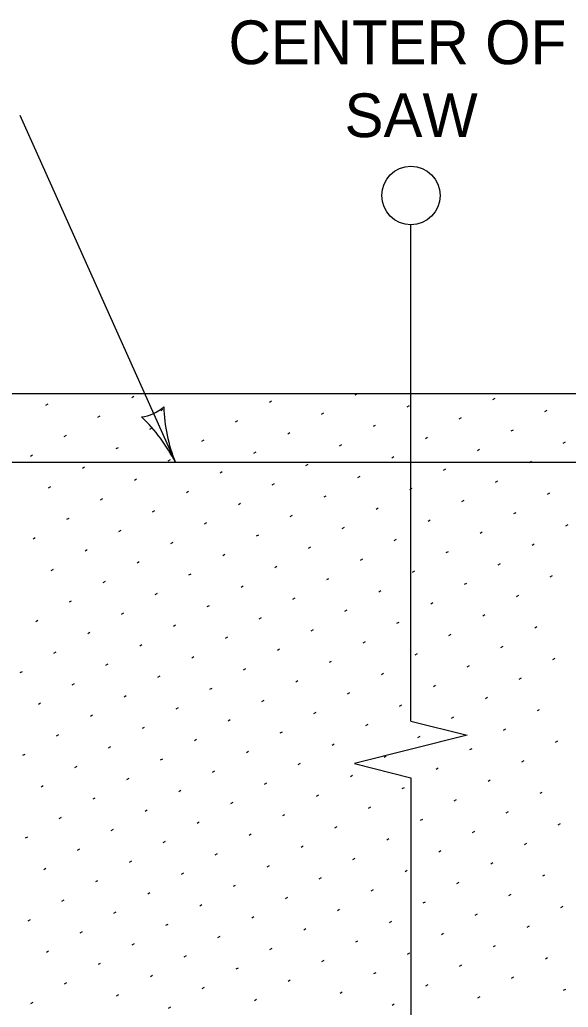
# Model space of a CAD drawing. Extents: x 49991.4 to 50021, y 49987.6 to 50011.4.
# Drawn here: x 50004.089 to 50004.842, y 49994.036 to 49995.39 of the extents above; entities that cross this region are included whole.
import ezdxf

# ---------------------------------------------------------------- set-up
doc = ezdxf.new("R2010")
doc.units = 0
for name, color, linetype in [('Level 1', 7, 'Continuous'), ('Level 15', 7, 'Continuous'), ('Level 3', 7, 'Continuous')]:
    doc.layers.add(name, color=color, linetype=linetype)

msp = doc.modelspace()

# ---------------------------------------------------------------- linework, layer by layer
at = {"layer": 'Level 1'}
for p, q in [((50002.5376, 49994.8772), (50004.5362, 49994.8772)), ((50004.5362, 49994.8772), (50008.0315, 49994.8772)), ((50008.0315, 49994.7828), (50001.9803, 49994.7828))]:
    msp.add_line(p, q, dxfattribs=at)
msp.add_ellipse((50004.6259, 49996.2377), major_axis=(0, -2.952), ratio=0.83118, start_param=5.208402, end_param=6.283185, dxfattribs=at)
at = {"layer": 'Level 15'}
msp.add_line((50004.6259, 49994.3507), (50004.6259, 49994.0829), dxfattribs=at)
at = {"layer": 'Level 3'}
for p, q in [((50004.0891, 49995.2588), (50004.3027, 49994.7828)), ((50004.6259, 49994.4281), (50004.6259, 49995.1088)), ((50004.5495, 49994.8757), (50004.5521, 49994.8772)), ((50004.1251, 49994.8616), (50004.1281, 49994.8634)), ((50004.2428, 49994.8718), (50004.2458, 49994.8736)), ((50004.4318, 49994.8655), (50004.4348, 49994.8672)), ((50004.7385, 49994.8693), (50004.7415, 49994.8711)), ((50004.2834, 49994.8536), (50004.2855, 49994.8564)), ((50004.5031, 49994.8489), (50004.5062, 49994.8507)), ((50004.6208, 49994.8591), (50004.6238, 49994.8609)), ((50004.8098, 49994.8528), (50004.8128, 49994.8545)), ((50004.1964, 49994.8451), (50004.1995, 49994.8468)), ((50004.3854, 49994.8387), (50004.3885, 49994.8405)), ((50004.6921, 49994.8426), (50004.6952, 49994.8443)), ((50004.2678, 49994.8285), (50004.2708, 49994.8303)), ((50004.4568, 49994.8222), (50004.4598, 49994.8239)), ((50004.5745, 49994.8324), (50004.5775, 49994.8341)), ((50004.7635, 49994.826), (50004.7665, 49994.8278)), ((50004.1501, 49994.8183), (50004.1531, 49994.8201)), ((50004.3391, 49994.812), (50004.3421, 49994.8137)), ((50004.6458, 49994.8158), (50004.6488, 49994.8176)), ((50004.8348, 49994.8095), (50004.8378, 49994.8112)), ((50004.2214, 49994.8018), (50004.2245, 49994.8035)), ((50004.4104, 49994.7954), (50004.4135, 49994.7972)), ((50004.5281, 49994.8056), (50004.5312, 49994.8074)), ((50004.7171, 49994.7993), (50004.7202, 49994.801)), ((50004.1038, 49994.7916), (50004.1068, 49994.7933)), ((50004.2928, 49994.7852), (50004.2958, 49994.787)), ((50004.5995, 49994.7891), (50004.6025, 49994.7908)), ((50004.7885, 49994.7827), (50004.7915, 49994.7845)), ((50004.1751, 49994.775), (50004.1781, 49994.7768)), ((50004.3641, 49994.7687), (50004.3671, 49994.7704)), ((50004.4818, 49994.7789), (50004.4848, 49994.7806)), ((50004.6708, 49994.7725), (50004.6738, 49994.7743)), ((50004.2464, 49994.7585), (50004.2495, 49994.7602)), ((50004.5531, 49994.7623), (50004.5562, 49994.7641)), ((50004.7421, 49994.756), (50004.7452, 49994.7577)), ((50004.1288, 49994.7483), (50004.1318, 49994.75)), ((50004.3178, 49994.7419), (50004.3208, 49994.7437)), ((50004.4354, 49994.7521), (50004.4385, 49994.7539)), ((50004.6245, 49994.7458), (50004.6275, 49994.7475)), ((50004.2001, 49994.7317), (50004.2031, 49994.7335)), ((50004.5068, 49994.7356), (50004.5098, 49994.7373)), ((50004.6958, 49994.7292), (50004.6988, 49994.731)), ((50004.8135, 49994.7394), (50004.8165, 49994.7412)), ((50004.2714, 49994.7152), (50004.2745, 49994.7169)), ((50004.3891, 49994.7254), (50004.3921, 49994.7271)), ((50004.5781, 49994.719), (50004.5812, 49994.7208)), ((50004.7671, 49994.7127), (50004.7702, 49994.7144)), ((50004.1538, 49994.705), (50004.1568, 49994.7067)), ((50004.4604, 49994.7088), (50004.4635, 49994.7106)), ((50004.6495, 49994.7025), (50004.6525, 49994.7042)), ((50004.2251, 49994.6884), (50004.2281, 49994.6902)), ((50004.3428, 49994.6986), (50004.3458, 49994.7004)), ((50004.5318, 49994.6923), (50004.5348, 49994.694)), ((50004.7208, 49994.6859), (50004.7238, 49994.6877)), ((50004.8385, 49994.6961), (50004.8415, 49994.6979)), ((50004.1074, 49994.6782), (50004.1104, 49994.68)), ((50004.4141, 49994.6821), (50004.4171, 49994.6838)), ((50004.6031, 49994.6757), (50004.6062, 49994.6775)), ((50004.1788, 49994.6617), (50004.1818, 49994.6634)), ((50004.2964, 49994.6719), (50004.2995, 49994.6736)), ((50004.4854, 49994.6655), (50004.4885, 49994.6673)), ((50004.6745, 49994.6592), (50004.6775, 49994.6609)), ((50004.7921, 49994.6694), (50004.7952, 49994.6711)), ((50004.2501, 49994.6451), (50004.2531, 49994.6469)), ((50004.3678, 49994.6553), (50004.3708, 49994.6571)), ((50004.5568, 49994.649), (50004.5598, 49994.6507)), ((50004.1324, 49994.6349), (50004.1354, 49994.6366)), ((50004.4391, 49994.6388), (50004.4421, 49994.6405)), ((50004.6281, 49994.6324), (50004.6312, 49994.6342)), ((50004.7458, 49994.6426), (50004.7488, 49994.6444)), ((50004.2038, 49994.6184), (50004.2068, 49994.6201)), ((50004.3214, 49994.6286), (50004.3245, 49994.6303)), ((50004.5104, 49994.6222), (50004.5135, 49994.624)), ((50004.8171, 49994.6261), (50004.8202, 49994.6278)), ((50004.3928, 49994.612), (50004.3958, 49994.6138)), ((50004.5818, 49994.6057), (50004.5848, 49994.6074)), ((50004.6995, 49994.6159), (50004.7025, 49994.6176)), ((50004.1574, 49994.5916), (50004.1604, 49994.5933)), ((50004.2751, 49994.6018), (50004.2781, 49994.6036)), ((50004.4641, 49994.5955), (50004.4671, 49994.5972)), ((50004.7708, 49994.5993), (50004.7738, 49994.6011)), ((50004.3464, 49994.5853), (50004.3495, 49994.587)), ((50004.5354, 49994.5789), (50004.5385, 49994.5807)), ((50004.6531, 49994.5891), (50004.6562, 49994.5909)), ((50004.1111, 49994.5648), (50004.1141, 49994.5666)), ((50004.2288, 49994.575), (50004.2318, 49994.5768)), ((50004.4178, 49994.5687), (50004.4208, 49994.5705)), ((50004.7245, 49994.5726), (50004.7275, 49994.5743)), ((50004.3001, 49994.5585), (50004.3031, 49994.5603)), ((50004.4891, 49994.5522), (50004.4921, 49994.5539)), ((50004.6068, 49994.5624), (50004.6098, 49994.5641)), ((50004.7958, 49994.556), (50004.7988, 49994.5578)), ((50004.1824, 49994.5483), (50004.1854, 49994.55)), ((50004.3714, 49994.542), (50004.3745, 49994.5437)), ((50004.6781, 49994.5458), (50004.6812, 49994.5476)), ((50004.2538, 49994.5317), (50004.2568, 49994.5335)), ((50004.4428, 49994.5254), (50004.4458, 49994.5272)), ((50004.5604, 49994.5356), (50004.5635, 49994.5374)), ((50004.7495, 49994.5293), (50004.7525, 49994.531)), ((50004.1361, 49994.5215), (50004.1391, 49994.5233)), ((50004.3251, 49994.5152), (50004.3281, 49994.517)), ((50004.6318, 49994.5191), (50004.6348, 49994.5208)), ((50004.8208, 49994.5127), (50004.8238, 49994.5145)), ((50004.2074, 49994.505), (50004.2104, 49994.5067)), ((50004.3964, 49994.4987), (50004.3995, 49994.5004)), ((50004.5141, 49994.5089), (50004.5171, 49994.5106)), ((50004.7031, 49994.5025), (50004.7062, 49994.5043)), ((50004.0897, 49994.4948), (50004.0928, 49994.4965)), ((50004.2788, 49994.4884), (50004.2818, 49994.4902)), ((50004.5854, 49994.4923), (50004.5885, 49994.4941)), ((50004.7745, 49994.486), (50004.7775, 49994.4877)), ((50004.1611, 49994.4782), (50004.1641, 49994.48)), ((50004.3501, 49994.4719), (50004.3531, 49994.4736)), ((50004.4678, 49994.4821), (50004.4708, 49994.4839)), ((50004.6568, 49994.4758), (50004.6598, 49994.4775)), ((50004.2324, 49994.4617), (50004.2354, 49994.4634)), ((50004.5391, 49994.4656), (50004.5421, 49994.4673)), ((50004.7281, 49994.4592), (50004.7312, 49994.461)), ((50004.1147, 49994.4515), (50004.1178, 49994.4532)), ((50004.3038, 49994.4451), (50004.3068, 49994.4469)), ((50004.4214, 49994.4554), (50004.4245, 49994.4571)), ((50004.6104, 49994.449), (50004.6135, 49994.4508)), ((50004.7995, 49994.4427), (50004.8025, 49994.4444)), ((50004.1861, 49994.4349), (50004.1891, 49994.4367)), ((50004.3751, 49994.4286), (50004.3781, 49994.4303)), ((50004.4928, 49994.4388), (50004.4958, 49994.4406)), ((50004.6818, 49994.4325), (50004.6848, 49994.4342)), ((50004.2574, 49994.4184), (50004.2604, 49994.4201)), ((50004.5641, 49994.4223), (50004.5671, 49994.424)), ((50004.7531, 49994.4159), (50004.7562, 49994.4177)), ((50004.1397, 49994.4082), (50004.1428, 49994.4099)), ((50004.3288, 49994.4018), (50004.3318, 49994.4036)), ((50004.4464, 49994.4121), (50004.4495, 49994.4138)), ((50004.6354, 49994.4057), (50004.6385, 49994.4075)), ((50004.2111, 49994.3916), (50004.2141, 49994.3934)), ((50004.5178, 49994.3955), (50004.5208, 49994.3973)), ((50004.7068, 49994.3892), (50004.7098, 49994.3909)), ((50004.8245, 49994.3994), (50004.8275, 49994.4011)), ((50004.0934, 49994.3814), (50004.0964, 49994.3832)), ((50004.2824, 49994.3751), (50004.2854, 49994.3768)), ((50004.4001, 49994.3853), (50004.4031, 49994.387)), ((50004.5891, 49994.379), (50004.5921, 49994.3807)), ((50004.1647, 49994.3649), (50004.1678, 49994.3666)), ((50004.4714, 49994.3687), (50004.4745, 49994.3705)), ((50004.6604, 49994.3624), (50004.6635, 49994.3642)), ((50004.7781, 49994.3726), (50004.7812, 49994.3744)), ((50004.2361, 49994.3483), (50004.2391, 49994.3501)), ((50004.3538, 49994.3585), (50004.3568, 49994.3603)), ((50004.5428, 49994.3522), (50004.5458, 49994.354)), ((50004.1184, 49994.3381), (50004.1214, 49994.3399)), ((50004.4251, 49994.342), (50004.4281, 49994.3437)), ((50004.6141, 49994.3357), (50004.6171, 49994.3374)), ((50004.7318, 49994.3459), (50004.7348, 49994.3476)), ((50004.1897, 49994.3216), (50004.1928, 49994.3233)), ((50004.3074, 49994.3318), (50004.3104, 49994.3335)), ((50004.4964, 49994.3254), (50004.4995, 49994.3272)), ((50004.8031, 49994.3293), (50004.8062, 49994.3311)), ((50004.3788, 49994.3152), (50004.3818, 49994.317)), ((50004.5678, 49994.3089), (50004.5708, 49994.3107)), ((50004.6854, 49994.3191), (50004.6885, 49994.3209)), ((50004.1434, 49994.2948), (50004.1464, 49994.2966)), ((50004.2611, 49994.305), (50004.2641, 49994.3068)), ((50004.4501, 49994.2987), (50004.4531, 49994.3004)), ((50004.7568, 49994.3026), (50004.7598, 49994.3043)), ((50004.3324, 49994.2885), (50004.3354, 49994.2902)), ((50004.5214, 49994.2821), (50004.5245, 49994.2839)), ((50004.6391, 49994.2924), (50004.6421, 49994.2941)), ((50004.8281, 49994.286), (50004.8312, 49994.2878)), ((50004.0971, 49994.2681), (50004.1001, 49994.2698)), ((50004.2147, 49994.2783), (50004.2178, 49994.28)), ((50004.4038, 49994.2719), (50004.4068, 49994.2737)), ((50004.7104, 49994.2758), (50004.7135, 49994.2776)), ((50004.2861, 49994.2617), (50004.2891, 49994.2635)), ((50004.4751, 49994.2554), (50004.4781, 49994.2571)), ((50004.5928, 49994.2656), (50004.5958, 49994.2673)), ((50004.7818, 49994.2593), (50004.7848, 49994.261)), ((50004.1684, 49994.2515), (50004.1714, 49994.2533)), ((50004.3574, 49994.2452), (50004.3604, 49994.2469)), ((50004.6641, 49994.2491), (50004.6671, 49994.2508)), ((50004.2397, 49994.235), (50004.2428, 49994.2367)), ((50004.4288, 49994.2286), (50004.4318, 49994.2304)), ((50004.5464, 49994.2388), (50004.5495, 49994.2406)), ((50004.7354, 49994.2325), (50004.7385, 49994.2343)), ((50004.1221, 49994.2248), (50004.1251, 49994.2265)), ((50004.3111, 49994.2184), (50004.3141, 49994.2202)), ((50004.5001, 49994.2121), (50004.5031, 49994.2138)), ((50004.6178, 49994.2223), (50004.6208, 49994.224)), ((50004.8068, 49994.216), (50004.8098, 49994.2177)), ((50004.1934, 49994.2082), (50004.1964, 49994.21)), ((50004.3824, 49994.2019), (50004.3854, 49994.2036)), ((50004.6891, 49994.2057), (50004.6921, 49994.2075)), ((50004.2647, 49994.1917), (50004.2678, 49994.1934)), ((50004.4538, 49994.1853), (50004.4568, 49994.1871)), ((50004.5714, 49994.1955), (50004.5745, 49994.1973)), ((50004.7604, 49994.1892), (50004.7635, 49994.191)), ((50004.1471, 49994.1815), (50004.1501, 49994.1832)), ((50004.3361, 49994.1751), (50004.3391, 49994.1769)), ((50004.6428, 49994.179), (50004.6458, 49994.1807)), ((50004.8318, 49994.1727), (50004.8348, 49994.1744)), ((50004.2184, 49994.1649), (50004.2214, 49994.1667)), ((50004.4074, 49994.1586), (50004.4104, 49994.1603)), ((50004.5251, 49994.1688), (50004.5281, 49994.1705)), ((50004.7141, 49994.1624), (50004.7171, 49994.1642)), ((50004.1007, 49994.1547), (50004.1038, 49994.1565)), ((50004.2897, 49994.1484), (50004.2928, 49994.1501)), ((50004.5964, 49994.1522), (50004.5995, 49994.154)), ((50004.7854, 49994.1459), (50004.7885, 49994.1477)), ((50004.1721, 49994.1382), (50004.1751, 49994.1399)), ((50004.3611, 49994.1318), (50004.3641, 49994.1336)), ((50004.4788, 49994.142), (50004.4818, 49994.1438)), ((50004.6678, 49994.1357), (50004.6708, 49994.1374)), ((50004.2434, 49994.1216), (50004.2464, 49994.1234)), ((50004.5501, 49994.1255), (50004.5531, 49994.1272)), ((50004.7391, 49994.1191), (50004.7421, 49994.1209)), ((50004.1257, 49994.1114), (50004.1288, 49994.1132)), ((50004.3147, 49994.1051), (50004.3178, 49994.1068)), ((50004.4324, 49994.1153), (50004.4354, 49994.117)), ((50004.6214, 49994.1089), (50004.6245, 49994.1107)), ((50004.1971, 49994.0949), (50004.2001, 49994.0966)), ((50004.5038, 49994.0987), (50004.5068, 49994.1005)), ((50004.6928, 49994.0924), (50004.6958, 49994.0941)), ((50004.8104, 49994.1026), (50004.8135, 49994.1043)), ((50004.2684, 49994.0783), (50004.2714, 49994.0801)), ((50004.3861, 49994.0885), (50004.3891, 49994.0903)), ((50004.5751, 49994.0822), (50004.5781, 49994.0839)), ((50004.6259, 49994.0829), (50004.6259, 49993.3332)), ((50004.1507, 49994.0681), (50004.1538, 49994.0699)), ((50004.4574, 49994.072), (50004.4604, 49994.0737)), ((50004.6464, 49994.0656), (50004.6495, 49994.0674)), ((50004.7641, 49994.0758), (50004.7671, 49994.0776)), ((50004.2221, 49994.0516), (50004.2251, 49994.0533)), ((50004.3397, 49994.0618), (50004.3428, 49994.0635)), ((50004.5288, 49994.0554), (50004.5318, 49994.0572)), ((50004.8354, 49994.0593), (50004.8385, 49994.061)), ((50004.1044, 49994.0414), (50004.1074, 49994.0431)), ((50004.4111, 49994.0452), (50004.4141, 49994.047)), ((50004.6001, 49994.0389), (50004.6031, 49994.0406)), ((50004.7178, 49994.0491), (50004.7208, 49994.0508)), ((50004.2934, 49994.035), (50004.2964, 49994.0368))]:
    msp.add_line(p, q, dxfattribs=at)
msp.add_lwpolyline([(50004.6259, 49994.4281), (50004.7033, 49994.4088), (50004.5485, 49994.37), (50004.6259, 49994.3507)], dxfattribs=at)
msp.add_circle((50004.6259, 49995.1488), 0.04, dxfattribs=at)
for centre, radius, start, end in [((50004.2502, 49994.8998), 0.0548, 276.2982, 312.0206), ((50004.5091, 49994.8654), 0.2223, 181.6154, 201.7989), ((50004.0951, 49994.6771), 0.233, 26.9867, 46.2366)]:
    msp.add_arc(centre, radius, start, end, dxfattribs=at)

# ---------------------------------------------------------------- texts
for s, p in [('CENTER OF ', (50004.3756, 49995.3288)), ('SAW', (50004.5348, 49995.2288))]:
    msp.add_text(s, height=0.06, dxfattribs=at).set_placement(p)

doc.saveas('drawing.dxf')
